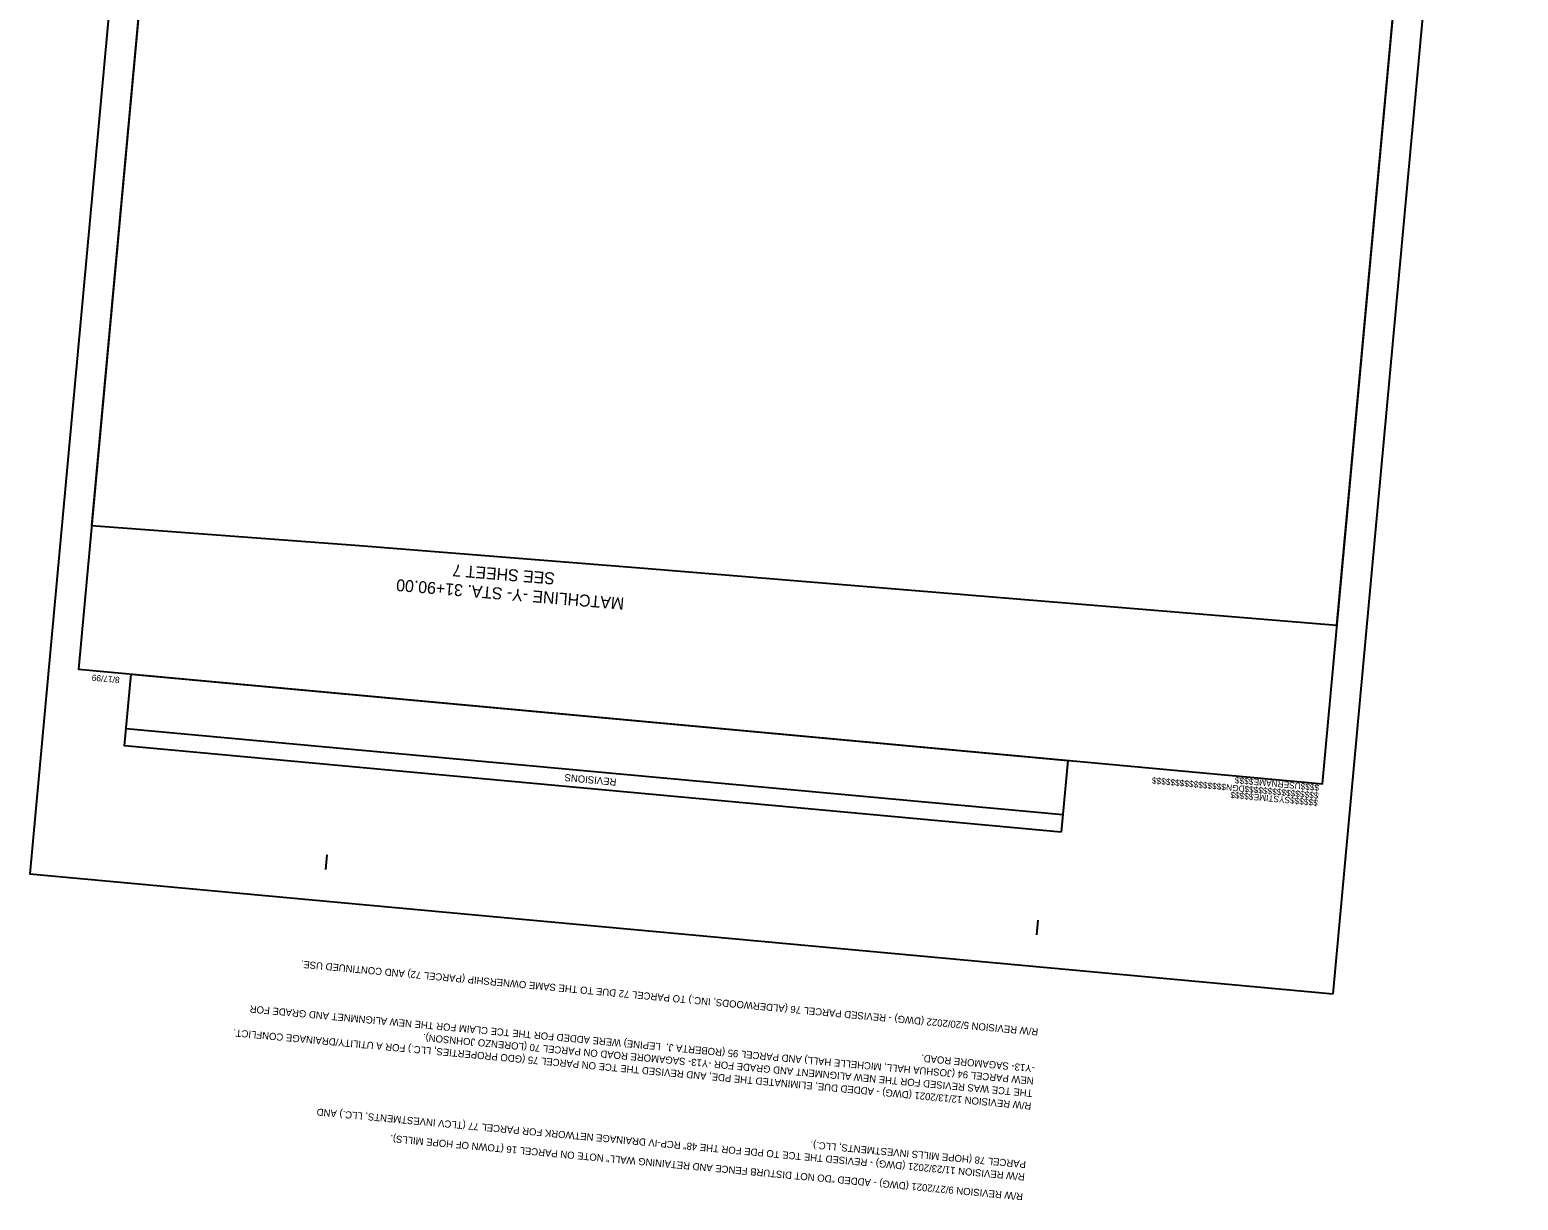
# Model space of a CAD drawing. Extents: x 2012234 to 2013485, y 445879 to 447846.
# Drawn here: x 2012234 to 2013485, y 445879 to 446862 of the extents above; entities that cross this region are included whole.
import ezdxf

# ---------------------------------------------------------------- set-up
doc = ezdxf.new("R2010")
doc.units = 0
for name, color, linetype in [('Matchline', 7, 'Continuous'), ('Matchline Text', 7, 'Continuous'), ('Old_Level_1', 7, 'Continuous'), ('Sheet Block Revision CELL', 7, 'Continuous'), ('Sheet Block System Information CELL', 7, 'Continuous'), ('Sheet Clip Boundary CELL', 7, 'Continuous'), ('Sheet Plan And Profile CELL', 7, 'Continuous'), ('Sheet Plot Border Outside CELL', 7, 'Continuous')]:
    doc.layers.add(name, color=color, linetype=linetype)

msp = doc.modelspace()

# ---------------------------------------------------------------- linework, layer by layer
at = {"layer": 'Matchline'}
msp.add_line((2012511.4, 446429.2), (2012750.7, 446410.1), dxfattribs=at)
at = {"layer": 'Sheet Block Revision CELL'}
msp.add_line((2013102.5, 446202.8), (2012315.2, 446275.2), dxfattribs=at)
msp.add_lwpolyline([(2013101.2, 446188.3), (2012313.8, 446260.7), (2012319.4, 446321), (2013106.7, 446248.6)], close=True, dxfattribs=at)
at = {"layer": 'Sheet Block System Information CELL'}
msp.add_line((2013320.8, 446228.9), (2013320.8, 446228.9), dxfattribs=at)
at = {"layer": 'Sheet Clip Boundary CELL'}
msp.add_lwpolyline([(2012286.3, 446445.8), (2012511.4, 446429.2), (2012750.7, 446410.1), (2013333, 446362.1), (2013458.1, 447722.6), (2012593.8, 447802.1), (2012575.5, 447602.9), (2012460.6, 447613.5), (2012442.3, 447414.3), (2012375.9, 447420.4)], close=True, dxfattribs=at)
at = {"layer": 'Sheet Plan And Profile CELL'}
for p, q in [((2013320.8, 446228.9), (2013320.8, 446228.9)), ((2013320.8, 446228.9), (2013320.8, 446228.9)), ((2013320.8, 446228.9), (2013320.8, 446228.9)), ((2013320.8, 446228.9), (2013320.8, 446228.9)), ((2013320.8, 446228.9), (2013320.8, 446228.9)), ((2012483.2, 446156.8), (2012484.3, 446169.3)), ((2013080.7, 446101.9), (2013081.8, 446114.3))]:
    msp.add_line(p, q, dxfattribs=at)
msp.add_lwpolyline([(2012412.6, 447818.8), (2012275.2, 446325.1), (2013320.8, 446228.9), (2013458.1, 447722.6)], close=True, dxfattribs=at)
at = {"layer": 'Sheet Plot Border Outside CELL'}
msp.add_lwpolyline([(2013329.7, 446052.4), (2013485.3, 447745.2), (2012389.9, 447846), (2012234.3, 446153.1)], close=True, dxfattribs=at)

# ---------------------------------------------------------------- texts
at = {"layer": 'Matchline Text'}
for s, p in [('SEE SHEET 7', (2012676, 446406.2)), ('MATCHLINE -Y- STA. 31+90.00', (2012734.2, 446385.1))]:
    msp.add_text(s, height=10, rotation=175.2749, dxfattribs=at).set_placement(p)
at = {"layer": 'Old_Level_1'}
for s, p in [('R/W REVISION 5/20/2022 (DWG) - REVISED PARCEL 76 (ALDERWOODS, INC.) TO PARCEL 72 DUE TO THE SAME OWNERSHIP (PARCEL 72) AND CONTINUED USE.  ', (2013082.1, 446023.3)), ('NEW PARCEL 94 (JOSHUA HALL, MICHELLE HALL) AND PARCEL 95 (ROBERTA J.  LEPINE) WERE ADDED FOR THE TCE CLAIM FOR THE NEW ALIGNMNET AND GRADE FOR ', (2013078.3, 445982.1)), ('R/W REVISION 12/13/2021 (DWG) - ADDED DUE, ELIMINATED THE PDE, AND REVISED THE TCE ON PARCEL 75 (GDO PROPERTIES, LLC.) FOR A UTILITY/DRAINAGE CONFLICT.  ', (2013076.3, 445961)), ('THE TCE WAS REVISED FOR THE NEW ALIGNMENT AND GRADE FOR -Y13- SAGAMORE ROAD ON PARCEL 70 (LORENZO JOHNSON).', (2013077.3, 445971.6)), ('-Y13- SAGAMORE ROAD.', (2013079.2, 445992.5)), ('R/W REVISION 11/23/2021 (DWG) - REVISED THE TCE TO PDE FOR THE 48" RCP-IV DRAINAGE NETWORK FOR PARCEL 77 (TLCV INVESTMENTS, LLC.) AND ', (2013070.8, 445901.4)), ('R/W REVISION 9/27/2021 (DWG) - ADDED "DO NOT DISTURB FENCE AND RETAINING WALL" NOTE ON PARCEL 16 (TOWN OF HOPE MILLS).', (2013069.3, 445884.9)), ('PARCEL 78 (HOPE MILLS INVESTMENTS, LLC.).', (2013071.8, 445911.9))]:
    msp.add_text(s, height=6, rotation=174.7467, dxfattribs=at).set_placement(p)
at = {"layer": 'Sheet Block Revision CELL'}
msp.add_text('REVISIONS', height=6, rotation=174.7467, dxfattribs=at).set_placement((2012727.6, 446233.2))
at = {"layer": 'Sheet Block System Information CELL'}
for s, p in [('$$$$$$$$$$$$$$$$DGN$$$$$$$$$$$$$$$$', (2013317.8, 446221.5)), ('$$$$USERNAME$$$$', (2013318.3, 446228.1)), ('$$$$$$SYSTIME$$$$$', (2013317.2, 446215.5))]:
    msp.add_text(s, height=5.25, rotation=174.7467, dxfattribs=at).set_placement(p)
at = {"layer": 'Sheet Plan And Profile CELL'}
msp.add_text('8/17/99', height=5.25, rotation=174.7467, dxfattribs=at).set_placement((2012310, 446318.6))

doc.saveas('drawing.dxf')
